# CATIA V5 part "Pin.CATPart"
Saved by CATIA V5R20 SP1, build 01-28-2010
Part number: Pin
Bounding box of the stored display mesh (mm): x -10.997 to 10.997, y 0 to 38, z -10.885 to 10.885
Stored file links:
  D:\v5_r20\psrt_files_downloaded\c14\c14-catia-v5r20-figr-14-26 & 27\Part & Asm\Pin.CATPart
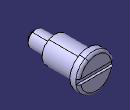
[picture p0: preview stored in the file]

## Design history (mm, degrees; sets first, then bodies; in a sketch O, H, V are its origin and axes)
Body1 (main body)
  Sketch1 on yz-plane, origin (0, 0, 0), H (0, 1, 0), V (0, 0, 1)
    line L1 (0, 0) -> (0, 5)
    line L2 (0, 5) -> (13, 5)
    line L3 (13, 5) -> (13, 8)
    line L4 (13, 8) -> (33, 8)
    line L5 (33, 8) -> (33, 11)
    line L6 (33, 11) -> (38, 11)
    line L7 (38, 11) -> (38, 0)
    point P7 (38, 0)
    line L8 (38, 0) -> (0, 0)
    distance L8 L6 = 11
    distance L4 L8 = 8
    length L8 = 38
    distance L2 L8 = 5
    length L6 = 5
    length L4 = 20
    vertical: L1 V, L3 V, L5 V, L7 V
    horizontal: L2 H, L4 H, L8 H, L6 H
    coincidence: P7 H
  Shaft1: profile Sketch1, axis edge of Sketch1, angle 360
  Chamfer1: length 1.5, angle 45, on 1 edge
  Fillet1: radius 1.5, on 1 edge
  Sketch2 on face of Shaft1, origin (0, 38, 0), H (-1, 0, 0), V (0, 0, 1)
    line L1 (-15.6575, 1.5) -> (20.3727, 1.5)
    line L2 (20.3727, 1.5) -> (20.3727, -1.5)
    line L3 (20.3727, -1.5) -> (-15.6575, -1.5)
    line L4 (-15.6575, -1.5) -> (-15.6575, 1.5)
    distance H L3 = 1.5
    length L4 = 3
    horizontal: L1 H, L3 H
    vertical: L2 V, L4 V
  Pocket1: profile Sketch2, direction (0, -1, 0), length 1.5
